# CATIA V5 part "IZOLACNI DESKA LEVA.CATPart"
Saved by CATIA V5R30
Part number: IZOLACNI DESKA LEVA
Bounding box of the stored display mesh (mm): x 0 to 8.5, y -173 to 173, z -273 to 273
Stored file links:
  C:\Users\ondra\Desktop\PŘÍLOHA P III\CATIA\IZOLACNI DESKA LEVA.CATPart
  C:\Users\ondra\Desktop\PŘÍLOHA P III\CATIA\FORMA.CATProduct
  C:\Users\ondra\Desktop\PŘÍLOHA P III\CATIA\UPINACI DESKA LEVA.CATPart
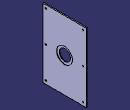
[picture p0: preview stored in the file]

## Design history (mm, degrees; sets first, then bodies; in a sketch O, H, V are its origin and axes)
Set1
  DatumSurface1 to DatumSurface6 "Z121/346"
  Join1: Elements (DatumSurface1; DatumSurface2; DatumSurface3; DatumSurface4; DatumSurface5; DatumSurface6)
Body1 (main body)
  Sketch1, origin (0, 0, 0), H (0, 0, 1), V (0, -1, 0), geometry linked from another document
  CloseSurface1: CloseElement Join1
  Sketch2 on {plane type Tangent, Support face of CloseSurface1, RefPoint vertex of Sketch1}, origin (0, 148, -248), H (0, 1, 0), V (0, 0, -1)
    point P1 (0, 0)
    reference projected point E1 (0, 0) from vertex of Sketch1
    coincidence: E1 P1
  Hole1: placed by Sketch2, at (8.5, 148, -248) direction (-1, 0, 0), diameter 6, through (limit type 6), countersink depth 3.3, countersink angle 90
  UserPattern1: of Hole1, copies 6, at the points of Sketch1
  Plane1: type Offset, RefPlane yz-plane, Offset 8.5
  Sketch3 on Plane1, origin (8.5, 0, 0), H (0, 1, 0), V (0, 0, 1)
    circle A1 centre (0, 0) radius 45
    radius A1 = 45
  Pocket1: profile Sketch3, direction (-1, 0, 0), through (limit type 6)
  Sketch4 on Plane1, origin (8.5, 0, 0), H (0, 1, 0), V (0, 0, 1)
    circle A1 centre (0, 0) radius 62.5
    radius A1 = 62.5
  Pocket2: profile Sketch4, direction (-1, 0, 0), length 3.5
